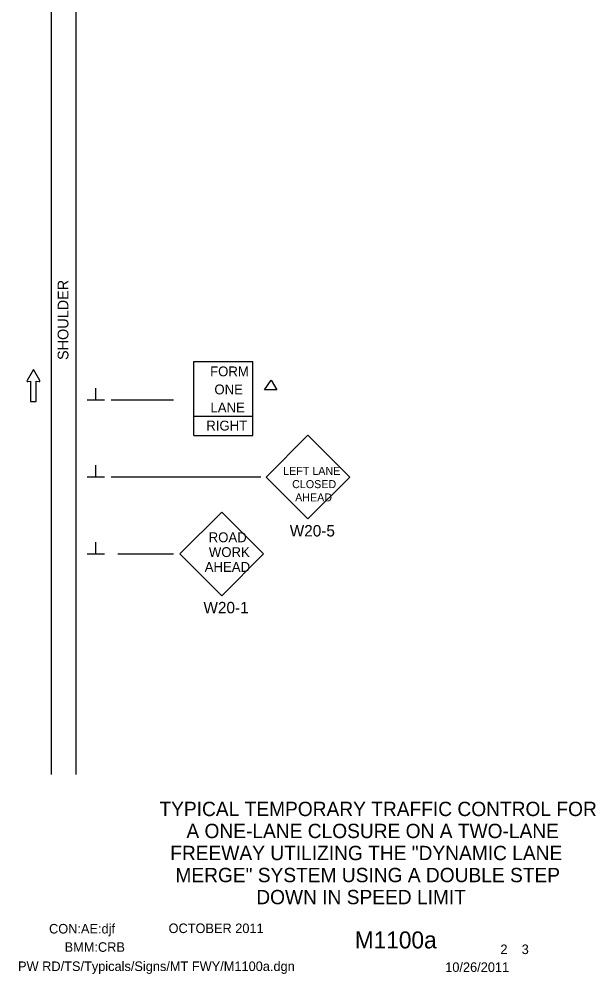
# Model space of a CAD drawing. Extents: x 15262 to 18126, y 1908 to 6555.
# Drawn here: x 16620 to 16994, y 2176 to 2796 of the extents above; entities that cross this region are included whole.
import ezdxf

# ---------------------------------------------------------------- set-up
doc = ezdxf.new("R2010")
doc.units = 0
for name, color, linetype in [('BORDER_SIGNAL_WO', 7, 'Continuous'), ('MT_SCRATCH_LEVEL_E', 7, 'Continuous'), ('PAVT_EDGE_EX', 7, 'Continuous'), ('TRAFFIC_SIGNS_PR', 7, 'Continuous'), ('TYPICAL_TEXT_DIMEN_PR', 7, 'Continuous')]:
    doc.layers.add(name, color=color, linetype=linetype)

msp = doc.modelspace()

# ---------------------------------------------------------------- linework, layer by layer
at = {"layer": 'MT_SCRATCH_LEVEL_E'}
for p, q in [((16628.88, 2568.38), (16624.77, 2561.14)), ((16633.03, 2561.14), (16628.88, 2568.38)), ((16625.25, 2560.45), (16627.03, 2560.77)), ((16627.03, 2560.77), (16627.03, 2547.51)), ((16630.77, 2547.51), (16630.77, 2560.77)), ((16630.77, 2560.77), (16632.55, 2560.45)), ((16627.03, 2547.51), (16630.77, 2547.51))]:
    msp.add_line(p, q, dxfattribs=at)
for centre, start, end in [((16625.17, 2560.91), 150.42484, 279.96381), ((16632.62, 2560.91), 260.03619, 29.77312)]:
    msp.add_arc(centre, 0.463, start, end, dxfattribs=at)
at = {"layer": 'PAVT_EDGE_EX'}
for p, q in [((16640.35, 3138.78), (16640.35, 2305.55)), ((16656.35, 3138.78), (16656.35, 2305.55))]:
    msp.add_line(p, q, dxfattribs=at)
at = {"layer": 'TRAFFIC_SIGNS_PR'}
for p, q in [((16733.1, 2525.54), (16733.1, 2573.5)), ((16733.1, 2573.5), (16771.46, 2573.5)), ((16771.46, 2525.54), (16771.46, 2573.5)), ((16733.1, 2537.95), (16771.46, 2537.95)), ((16733.1, 2525.54), (16771.46, 2525.54)), ((16807.18, 2525.7), (16780.03, 2498.55)), ((16834.33, 2498.55), (16807.18, 2525.7)), ((16780.03, 2498.55), (16807.18, 2471.4)), ((16807.18, 2471.4), (16834.33, 2498.55)), ((16751.15, 2475.85), (16724, 2448.69)), ((16778.3, 2448.69), (16751.15, 2475.85)), ((16724, 2448.69), (16751.15, 2421.54)), ((16751.15, 2421.54), (16778.3, 2448.69))]:
    msp.add_line(p, q, dxfattribs=at)
at = {"layer": 'TYPICAL_TEXT_DIMEN_PR'}
for p, q in [((16669.48, 2548.48), (16669.48, 2556.26)), ((16675.1, 2548.48), (16663.85, 2548.48)), ((16719.76, 2548.48), (16679.35, 2548.48)), ((16669.48, 2498.48), (16669.48, 2506.26)), ((16675.1, 2498.48), (16663.85, 2498.48)), ((16776.53, 2498.48), (16679.35, 2498.48)), ((16669.48, 2448.48), (16669.48, 2456.26)), ((16675.1, 2448.48), (16663.85, 2448.48)), ((16719.83, 2448.48), (16683.78, 2448.48))]:
    msp.add_line(p, q, dxfattribs=at)
msp.add_lwpolyline([(16778.97, 2555.15), (16783.33, 2561.45), (16787.03, 2555.15)], close=True, dxfattribs=at)

# ---------------------------------------------------------------- texts
at = {"layer": 'BORDER_SIGNAL_WO'}
for s, height, p in [('TYPICAL TEMPORARY TRAFFIC CONTROL FOR', 9.3, (16710.73, 2278.54)), ('A ONE-LANE CLOSURE ON A TWO-LANE', 9.3, (16728.24, 2264.24)), ('FREEWAY UTILIZING THE "DYNAMIC LANE', 9.3, (16717.74, 2249.94)), ('MERGE" SYSTEM USING A DOUBLE STEP ', 9.3, (16721.1, 2235.64)), ('DOWN IN SPEED LIMIT', 9.3, (16773.6, 2221.34)), ('CON:AE:djf  ', 6.2, (16639.05, 2202.35)), ('    OCTOBER 2011    ', 6.2, (16707.44, 2202.63)), ('    M1100a   ', 11, (16821.22, 2192.67)), ('BMM:CRB   ', 6.2, (16649.17, 2190.46)), (' 2    3 ', 6.2, (16929.81, 2188.99)), ('PW RD/TS/Typicals/Signs/MT FWY/M1100a.dgn      ', 6.2, (16618.92, 2178)), ('10/26/2011    ', 6.2, (16896.29, 2177.42))]:
    msp.add_text(s, height=height, dxfattribs=at).set_placement(p)
at = {"layer": 'TRAFFIC_SIGNS_PR'}
for s, height, p in [('FORM', 6.394, (16743.62, 2563.91)), ('ONE', 6.394, (16746.43, 2552.19)), ('LANE', 6.394, (16743.85, 2540.47)), ('RIGHT', 6.394, (16741.14, 2528.74)), ('LEFT LANE', 5.2, (16791.06, 2499.94)), ('CLOSED', 5.2, (16796.89, 2491.34)), ('AHEAD', 5.2, (16798.84, 2482.74)), ('W20-5', 7.44, (16795.36, 2459.96)), ('ROAD', 6.4, (16742.69, 2456.23)), ('WORK', 6.4, (16742.8, 2446.63)), ('AHEAD', 6.4, (16740.11, 2437.03)), ('W20-1', 7.44, (16739.32, 2410.1))]:
    msp.add_text(s, height=height, dxfattribs=at).set_placement(p)
at = {"layer": 'TYPICAL_TEXT_DIMEN_PR'}
msp.add_text('SHOULDER', height=7, rotation=90, dxfattribs=at).set_placement((16651.63, 2574.49))

doc.saveas('drawing.dxf')
